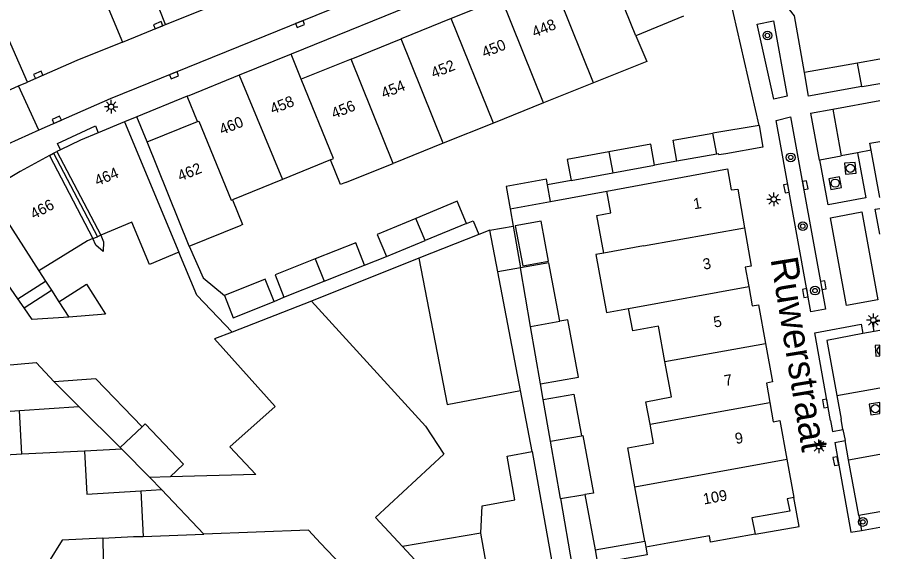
# Model space of a CAD drawing. Extents: x 132573 to 132944, y 398226 to 398676.
# Drawn here: x 132860.9 to 132940.1, y 398499.2 to 398548.2 of the extents above; entities that cross this region are included whole.
import ezdxf

# ---------------------------------------------------------------- set-up
doc = ezdxf.new("R2010")
doc.units = 0
for name, color, linetype in [('gg-afsc-erfafscheiding', 7, 'Continuous'), ('gg-afsc-muur', 7, 'Continuous'), ('gg-anno-huisnummerreeks BGT', 7, 'Continuous'), ('gg-anno-openbare ruimte label', 7, 'Continuous'), ('gg-bbg-bijgebouw', 7, 'Continuous'), ('gg-bbg-gedigitaliseerde bebouwing', 7, 'Continuous'), ('gg-bbg-gedigitaliseerde bebouwing onder overbouw', 7, 'Continuous'), ('gg-bbg-gedigitaliseerde bijgebouw', 7, 'Continuous'), ('gg-bbg-gedigitaliseerde overbouw', 7, 'Continuous'), ('gg-bbg-hoofdgebouw', 7, 'Continuous'), ('gg-bbg-luifel en loopbrug', 7, 'Continuous'), ('gg-bbg-onder overbouw', 7, 'Continuous'), ('gg-bbg-pand overbouw', 7, 'Continuous'), ('gg-bbg-tussenscheiding', 7, 'Continuous'), ('gg-bbg-tussenscheiding niveau 01', 7, 'Continuous'), ('gg-knt-verharding', 7, 'Continuous'), ('gg-knt-verharding nz', 7, 'Continuous'), ('gt-grn-groengrens', 7, 'Continuous'), ('gt-grn-vlakafsluiter', 7, 'Continuous'), ('gt-symb-boom', 7, 'Continuous'), ('gt-symb-kolk', 7, 'Continuous'), ('gt-symb-lichtmast', 7, 'Continuous'), ('gt-symb-rioolschacht', 7, 'Continuous')]:
    doc.layers.add(name, color=color, linetype=linetype)

msp = doc.modelspace()

# ---------------------------------------------------------------- linework, layer by layer
at = {"layer": 'gg-afsc-erfafscheiding'}
for p, q in [((132935.81, 398539.812), (132940.113, 398540.585)), ((132872.84, 398536.791), (132871.907, 398539.109)), ((132921.48, 398535.02), (132919.435, 398534.65)), ((132911.764, 398533.25), (132909.597, 398532.873)), ((132909.879, 398531.328), (132915.05, 398532.29)), ((132906.177, 398530.652), (132906.455, 398529.076)), ((132897.805, 398526.121), (132887.947, 398522.194)), ((132892.815, 398525.497), (132894.826, 398526.271)), ((132884.508, 398522.164), (132885.409, 398522.562)), ((132909.222, 398513.164), (132908.973, 398514.593)), ((132908.194, 398508.399), (132907.122, 398513.989))]:
    msp.add_line(p, q, dxfattribs=at)
for points in [[(132902.158, 398529.307), (132902.784, 398529.566), (132903.303, 398528.311)], [(132868.587, 398528.231), (132868.838, 398527.631), (132868.798, 398526.758), (132868.12, 398527.33), (132867.868, 398527.93)], [(132880.657, 398519.357), (132877.407, 398522.74), (132875.762, 398526.67)], [(132876.699, 398527.229), (132877.995, 398524.337), (132879.932, 398522.722)]]:
    msp.add_lwpolyline(points, dxfattribs=at)
at = {"layer": 'gg-afsc-muur'}
for p, q in [((132929.03, 398538.312), (132926.35, 398550.101)), ((132939.322, 398536.029), (132938.057, 398535.785)), ((132938.057, 398535.785), (132936.573, 398535.511)), ((132932.699, 398501.529), (132932.228, 398504.167)), ((132928.662, 398500.829), (132932.699, 398501.529))]:
    msp.add_line(p, q, dxfattribs=at)
msp.add_lwpolyline([(132933.193, 398543.17), (132932.27, 398548.361), (132931.02, 398549.991), (132930.646, 398551.538)], dxfattribs=at)
at = {"layer": 'gg-bbg-bijgebouw'}
for p, q in [((132938.075, 398544.033), (132933.193, 398543.17)), ((132940.113, 398544.393), (132938.075, 398544.033)), ((132933.58, 398540.991), (132933.193, 398543.17)), ((132938.47, 398541.864), (132933.58, 398540.991)), ((132938.47, 398541.864), (132938.491, 398541.868)), ((132938.491, 398541.868), (132940.113, 398542.157)), ((132933.759, 398539.438), (132935.81, 398539.812)), ((132935.81, 398539.812), (132936.573, 398535.511)), ((132929.03, 398538.312), (132924.8, 398537.585)), ((132929.03, 398538.312), (132929.383, 398536.329)), ((132929.383, 398536.329), (132925.981, 398535.715)), ((132925.142, 398535.679), (132921.48, 398535.02)), ((132934.605, 398535.141), (132936.573, 398535.511)), ((132902.158, 398529.307), (132898.375, 398527.741)), ((132894.826, 398526.271), (132898.375, 398527.741)), ((132889.109, 398524.028), (132892.815, 398525.497)), ((132885.409, 398522.562), (132889.109, 398524.028))]:
    msp.add_line(p, q, dxfattribs=at)
for points in [[(132933.759, 398539.438), (132934.554, 398535.131), (132934.605, 398535.141)], [(132921.48, 398535.02), (132921.143, 398536.956), (132924.8, 398537.585)], [(132925.981, 398535.715), (132925.337, 398535.599), (132925.317, 398535.71), (132925.142, 398535.679)], [(132902.158, 398529.307), (132901.317, 398531.35), (132897.53, 398529.782)], [(132897.53, 398529.782), (132893.98, 398528.311), (132894.826, 398526.271)], [(132892.815, 398525.497), (132892.002, 398527.551), (132888.274, 398526.074)], [(132888.274, 398526.074), (132884.595, 398524.616), (132885.409, 398522.562)], [(132884.508, 398522.164), (132883.693, 398524.215), (132879.932, 398522.722)], [(132879.932, 398522.722), (132880.749, 398520.67), (132884.508, 398522.164)]]:
    msp.add_lwpolyline(points, dxfattribs=at)
at = {"layer": 'gg-bbg-gedigitaliseerde bebouwing'}
for p, q in [((132870.75, 398538.641), (132875.762, 398526.67)), ((132862.911, 398524.963), (132863.512, 398524.031)), ((132860.969, 398522.391), (132863.512, 398524.031)), ((132887.947, 398522.194), (132880.657, 398519.357)), ((132874.958, 398506.073), (132873.101, 398506.023))]:
    msp.add_line(p, q, dxfattribs=at)
for points in [[(132914.764, 398526.589), (132914.132, 398530.046), (132915.422, 398530.283), (132915.05, 398532.29)], [(132875.762, 398526.67), (132873.068, 398525.542), (132871.441, 398529.427), (132868.587, 398528.231)], [(132867.868, 398527.93), (132867.363, 398527.718), (132862.911, 398524.963)], [(132914.764, 398526.589), (132914.046, 398526.457), (132915.032, 398521.152), (132917.051, 398521.52)], [(132860.969, 398522.391), (132858.839, 398525.456), (132855.502, 398523.243)], [(132880.657, 398519.357), (132879.037, 398518.727), (132884.59, 398512.541), (132880.441, 398508.817), (132882.835, 398506.285), (132874.958, 398506.073)]]:
    msp.add_lwpolyline(points, dxfattribs=at)
at = {"layer": 'gg-bbg-gedigitaliseerde bebouwing onder overbouw'}
for p, q in [((132863.872, 398535.546), (132867.868, 398527.93)), ((132864.562, 398535.903), (132868.587, 398528.231))]:
    msp.add_line(p, q, dxfattribs=at)
at = {"layer": 'gg-bbg-gedigitaliseerde bijgebouw'}
for p, q in [((132915.6, 398533.95), (132919.435, 398534.65)), ((132911.764, 398533.25), (132915.6, 398533.95)), ((132909.879, 398531.328), (132909.597, 398532.873)), ((132906.177, 398530.652), (132909.879, 398531.328)), ((132904.299, 398528.708), (132906.455, 398529.076)), ((132906.455, 398529.076), (132907.132, 398525.246)), ((132905.032, 398524.887), (132904.299, 398528.708)), ((132907.132, 398525.246), (132905.032, 398524.887)), ((132908.055, 398519.873), (132907.132, 398525.246)), ((132861.544, 398521.564), (132864.058, 398523.185)), ((132864.058, 398523.185), (132864.747, 398522.116)), ((132908.973, 398514.593), (132908.055, 398519.873)), ((132909.222, 398513.164), (132912.03, 398513.672)), ((132909.888, 398509.339), (132909.222, 398513.164)), ((132912.03, 398513.672), (132912.74, 398509.851)), ((132859.837, 398512.077), (132861.118, 398512.163)), ((132861.347, 398508.149), (132861.118, 398512.163)), ((132870.361, 398508.753), (132872.384, 398510.673)), ((132910.803, 398504.077), (132909.888, 398509.339)), ((132867.085, 398508.432), (132861.347, 398508.149)), ((132870.513, 398508.601), (132870.361, 398508.753)), ((132873.101, 398506.023), (132870.513, 398508.601)), ((132872.265, 398504.788), (132872.489, 398500.6)), ((132913.031, 398504.441), (132913.97, 398499.388)), ((132910.803, 398504.077), (132911.885, 398497.862)), ((132913.97, 398499.388), (132914.203, 398498.133))]:
    msp.add_line(p, q, dxfattribs=at)
for points in [[(132919.435, 398534.65), (132919.083, 398536.58), (132915.247, 398535.88)], [(132915.247, 398535.88), (132911.412, 398535.18), (132911.764, 398533.25)], [(132909.597, 398532.873), (132909.503, 398533.388), (132905.801, 398532.712), (132906.177, 398530.652)], [(132909.708, 398525.861), (132909.026, 398529.527), (132906.647, 398529.11), (132907.333, 398525.419), (132909.708, 398525.861)], [(132910.733, 398520.348), (132909.737, 398525.703), (132907.132, 398525.246)], [(132864.747, 398522.116), (132867.267, 398523.742), (132869.035, 398521.001), (132865.642, 398520.73)], [(132865.642, 398520.73), (132862.286, 398520.497), (132861.544, 398521.564)], [(132908.973, 398514.593), (132912.45, 398515.223), (132911.472, 398520.485), (132910.733, 398520.348)], [(132859.837, 398512.077), (132859.565, 398516.283), (132862.643, 398516.565), (132864.298, 398514.792)], [(132872.384, 398510.673), (132868.143, 398515.06), (132864.298, 398514.792)], [(132912.74, 398509.851), (132912.86, 398509.872), (132913.844, 398504.574), (132913.031, 398504.441)], [(132867.085, 398508.432), (132867.307, 398504.488), (132872.265, 398504.788)], [(132868.782, 398500.461), (132868.822, 398496.592), (132867.181, 398496.546), (132866.33, 398495.702)], [(132868.782, 398500.461), (132871.588, 398500.6), (132872.489, 398500.6)]]:
    msp.add_lwpolyline(points, dxfattribs=at)
at = {"layer": 'gg-bbg-gedigitaliseerde overbouw'}
for p in [(132867.868, 398527.93), (132868.587, 398528.231)]:
    msp.add_line(p, (132868.275, 398528.1), dxfattribs=at)
at = {"layer": 'gg-bbg-hoofdgebouw'}
for p, q in [((132905.367, 398549.981), (132900.775, 398548.121)), ((132900.775, 398548.121), (132896.183, 398546.261)), ((132922.085, 398548.337), (132917.731, 398546.536)), ((132891.592, 398544.401), (132896.183, 398546.261)), ((132886.06, 398544.851), (132881.304, 398542.92)), ((132887, 398542.541), (132886.06, 398544.851)), ((132891.592, 398544.401), (132887, 398542.541)), ((132881.304, 398542.92), (132876.66, 398541.034)), ((132913.827, 398542.218), (132909.23, 398540.371)), ((132876.66, 398541.034), (132876.53, 398540.981)), ((132877.47, 398538.661), (132876.53, 398540.981)), ((132909.23, 398540.371), (132904.633, 398538.523)), ((132870.75, 398538.641), (132868.354, 398537.642)), ((132872.84, 398536.791), (132877.47, 398538.661)), ((132904.633, 398538.523), (132900.037, 398536.676)), ((132876.699, 398527.229), (132872.84, 398536.791)), ((132939.205, 398536.674), (132940.113, 398536.837)), ((132864.884, 398536.061), (132864.562, 398535.903)), ((132900.037, 398536.676), (132895.44, 398534.827)), ((132939.322, 398536.029), (132939.205, 398536.674)), ((132940.113, 398531.685), (132939.322, 398536.029)), ((132889.682, 398535.15), (132885.261, 398533.355)), ((132891.059, 398533.067), (132895.44, 398534.827)), ((132915.05, 398532.29), (132926.12, 398534.333)), ((132885.261, 398533.355), (132880.678, 398531.494)), ((132876.699, 398527.229), (132881.468, 398529.17)), ((132908.194, 398508.399), (132909.704, 398500)), ((132931.59, 398507.692), (132932.228, 398504.167)), ((132918.532, 398500.182), (132917.627, 398505.17)), ((132909.704, 398500), (132910.135, 398497.605)), ((132918.532, 398500.182), (132918.63, 398499.639)), ((132920.664, 398500), (132918.63, 398499.639))]:
    msp.add_line(p, q, dxfattribs=at)
for points in [[(132917.731, 398546.536), (132918.719, 398544.185), (132913.827, 398542.218)], [(132868.354, 398537.642), (132866.72, 398536.961), (132864.884, 398536.061)], [(132863.872, 398535.546), (132861.179, 398534.096), (132858.174, 398532.307)], [(132891.059, 398533.067), (132890.602, 398532.883), (132889.682, 398535.15)], [(132926.12, 398534.333), (132926.469, 398532.387), (132927.069, 398532.476), (132927.696, 398528.93)], [(132880.678, 398531.494), (132881.598, 398529.223), (132881.468, 398529.17)], [(132940.113, 398528.329), (132939.697, 398530.623), (132940.113, 398530.698)], [(132927.696, 398528.93), (132928.318, 398525.414), (132927.758, 398525.301), (132928.082, 398523.529)], [(132928.082, 398523.529), (132928.403, 398521.77), (132928.993, 398521.847), (132929.637, 398518.305)], [(132887.947, 398522.194), (132898.401, 398510.734), (132900.085, 398508.167), (132893.819, 398502.346), (132896.299, 398499.682)], [(132920.39, 398516.661), (132919.788, 398519.903), (132917.433, 398519.465), (132917.051, 398521.52)], [(132929.637, 398518.305), (132930.278, 398514.784), (132929.699, 398514.66), (132930.021, 398512.888)], [(132919.021, 398510.922), (132918.64, 398512.969), (132920.995, 398513.407), (132920.39, 398516.661)], [(132930.021, 398512.888), (132930.341, 398511.125), (132930.948, 398511.234), (132931.59, 398507.692)], [(132917.627, 398505.17), (132916.983, 398508.722), (132919.348, 398509.162), (132919.021, 398510.922)], [(132903.474, 398500.903), (132903.601, 398503.404), (132906.602, 398503.958), (132905.893, 398507.977), (132908.194, 398508.399)], [(132932.228, 398504.167), (132931.627, 398504.061), (132931.842, 398502.937), (132928.382, 398502.323), (132928.662, 398500.829)], [(132928.662, 398500.829), (132924.579, 398500.086), (132924.472, 398500.676), (132920.664, 398500)]]:
    msp.add_lwpolyline(points, dxfattribs=at)
at = {"layer": 'gg-bbg-luifel en loopbrug'}
for p, q in [((132903.303, 398528.311), (132897.805, 398526.121)), ((132904.299, 398528.708), (132903.303, 398528.311)), ((132907.122, 398513.989), (132905.032, 398524.887)), ((132863.512, 398524.031), (132864.058, 398523.185)), ((132861.544, 398521.564), (132860.969, 398522.391)), ((132913.97, 398499.388), (132918.532, 398500.182))]:
    msp.add_line(p, q, dxfattribs=at)
for points in [[(132897.805, 398526.121), (132900.38, 398512.696), (132907.122, 398513.989)], [(132861.347, 398508.149), (132859.851, 398508.075), (132859.654, 398512.068), (132859.837, 398512.077)], [(132872.384, 398510.673), (132872.663, 398510.942), (132876.184, 398507.239), (132874.958, 398506.073)], [(132868.782, 398500.461), (132865.027, 398500.275), (132863.798, 398498.252)], [(132918.63, 398499.639), (132918.757, 398498.925), (132914.203, 398498.133)]]:
    msp.add_lwpolyline(points, dxfattribs=at)
at = {"layer": 'gg-bbg-onder overbouw'}
for points in [[(132904.422, 398493.346), (132904.388, 398493.537), (132904.506, 398493.558), (132904.463, 398493.843), (132904.75, 398493.886), (132903.474, 398500.903)], [(132901.235, 398492.774), (132901.192, 398492.963), (132901.075, 398492.936), (132900.469, 398495.203), (132896.299, 398499.682)]]:
    msp.add_lwpolyline(points, dxfattribs=at)
at = {"layer": 'gg-bbg-pand overbouw'}
for p, q in [((132863.872, 398535.546), (132864.259, 398535.754)), ((132864.259, 398535.754), (132864.562, 398535.903)), ((132903.474, 398500.903), (132896.299, 398499.682))]:
    msp.add_line(p, q, dxfattribs=at)
at = {"layer": 'gg-bbg-tussenscheiding'}
for p, q in [((132913.827, 398542.218), (132909.958, 398551.841)), ((132909.23, 398540.371), (132905.367, 398549.981)), ((132904.633, 398538.523), (132900.775, 398548.121)), ((132900.037, 398536.676), (132896.183, 398546.261)), ((132895.44, 398534.827), (132891.592, 398544.401)), ((132938.47, 398541.864), (132938.075, 398544.033)), ((132881.304, 398542.92), (132885.261, 398533.355)), ((132925.142, 398535.679), (132924.8, 398537.585)), ((132915.247, 398535.88), (132915.6, 398533.95)), ((132858.174, 398532.307), (132862.911, 398524.963)), ((132898.375, 398527.741), (132897.53, 398529.782)), ((132918.421, 398527.258), (132927.696, 398528.93)), ((132918.421, 398527.258), (132914.764, 398526.589)), ((132888.274, 398526.074), (132889.109, 398524.028)), ((132917.051, 398521.52), (132928.082, 398523.529)), ((132864.747, 398522.116), (132865.642, 398520.73)), ((132908.055, 398519.873), (132910.733, 398520.348)), ((132920.39, 398516.661), (132929.637, 398518.305)), ((132866.57, 398512.529), (132864.298, 398514.792)), ((132861.118, 398512.163), (132866.57, 398512.529)), ((132870.361, 398508.753), (132866.57, 398512.529)), ((132919.021, 398510.922), (132930.021, 398512.888)), ((132909.888, 398509.339), (132912.74, 398509.851)), ((132870.513, 398508.601), (132867.085, 398508.432)), ((132917.627, 398505.17), (132931.59, 398507.692)), ((132874.166, 398504.903), (132873.101, 398506.023)), ((132872.265, 398504.788), (132874.166, 398504.903)), ((132874.166, 398504.903), (132878.06, 398500.809)), ((132910.803, 398504.077), (132913.031, 398504.441)), ((132872.489, 398500.6), (132878.06, 398500.809)), ((132891.398, 398497.229), (132888.777, 398500))]:
    msp.add_line(p, q, dxfattribs=at)
for points in [[(132917.731, 398546.536), (132914.793, 398553.799), (132914.55, 398553.701)], [(132889.682, 398535.15), (132889.961, 398535.263), (132887, 398542.541)], [(132877.47, 398538.661), (132877.6, 398538.714), (132880.547, 398531.441), (132880.678, 398531.494)], [(132888.777, 398500), (132887.671, 398501.17), (132878.06, 398500.809)]]:
    msp.add_lwpolyline(points, dxfattribs=at)
at = {"layer": 'gg-bbg-tussenscheiding niveau 01'}
msp.add_line((132864.259, 398535.754), (132868.275, 398528.1), dxfattribs=at)
at = {"layer": 'gg-knt-verharding'}
for p, q in [((132913.61, 398556.031), (132886.06, 398544.851)), ((132874.532, 398547.556), (132872.221, 398553.404)), ((132868.18, 398551.756), (132870.582, 398545.942)), ((132861.856, 398542.29), (132859.304, 398548)), ((132870.582, 398545.942), (132874.532, 398547.556)), ((132861.045, 398541.93), (132861.856, 398542.29)), ((132862.897, 398537.875), (132861.045, 398541.93)), ((132876.53, 398540.981), (132871.907, 398539.109)), ((132871.907, 398539.109), (132870.75, 398538.641)), ((132862.897, 398537.875), (132858.535, 398535.906)), ((132933.796, 398521.196), (132931.013, 398536.586)), ((132940.113, 398519.496), (132939.591, 398519.403)), ((132935.602, 398511.242), (132934.14, 398519.294)), ((132936.172, 398513.526), (132936.568, 398511.374)), ((132935.602, 398511.242), (132935.788, 398510.241)), ((132936.727, 398510.433), (132936.568, 398511.374)), ((132935.788, 398510.241), (132936.727, 398510.433)), ((132935.976, 398509.228), (132936.933, 398509.398)), ((132935.976, 398509.228), (132937.46, 398500.988)), ((132937.251, 398507.648), (132936.933, 398509.398)), ((132938.19, 398502.527), (132937.251, 398507.648)), ((132940.113, 398502.879), (132938.19, 398502.527)), ((132937.46, 398500.988), (132938.44, 398501.165)), ((132938.44, 398501.165), (132940.113, 398501.468))]:
    msp.add_line(p, q, dxfattribs=at)
for points in [[(132922.48, 398562.197), (132915.452, 398559.401), (132869.443, 398540.745), (132862.897, 398537.875)], [(132928.866, 398547.6), (132930.357, 398547.898), (132931.602, 398540.994), (132930.399, 398540.729), (132928.866, 398547.6)], [(132856.665, 398539.883), (132858.71, 398540.892), (132861.045, 398541.93)], [(132931.013, 398536.586), (132930.616, 398538.77), (132931.932, 398539.091)], [(132931.932, 398539.091), (132935.129, 398521.454), (132933.796, 398521.196)], [(132864.884, 398536.061), (132864.602, 398536.636), (132868.096, 398538.26), (132868.354, 398537.642)], [(132938.057, 398535.785), (132938.833, 398531.668), (132935.367, 398531.015), (132934.605, 398535.141)], [(132935.593, 398529.84), (132938.46, 398530.369), (132939.93, 398522.32), (132937.055, 398521.793), (132935.593, 398529.84)], [(132939.591, 398519.403), (132939.443, 398520.26), (132940.113, 398520.384)], [(132934.14, 398519.294), (132938.417, 398520.077), (132938.571, 398519.222)], [(132938.571, 398519.222), (132935.26, 398518.593), (132936.172, 398513.526)]]:
    msp.add_lwpolyline(points, dxfattribs=at)
at = {"layer": 'gg-knt-verharding nz'}
for p, q in [((132874.532, 398547.556), (132883.53, 398551.178)), ((132936.172, 398513.526), (132940.113, 398514.241)), ((132937.251, 398507.648), (132940.113, 398508.168))]:
    msp.add_line(p, q, dxfattribs=at)
msp.add_lwpolyline([(132870.582, 398545.942), (132866.381, 398544.249), (132861.856, 398542.29)], dxfattribs=at)
at = {"layer": 'gt-grn-groengrens'}
msp.add_line((132938.19, 398502.527), (132938.44, 398501.165), dxfattribs=at)
at = {"layer": 'gt-grn-vlakafsluiter'}
for p, q in [((132939.591, 398519.403), (132938.571, 398519.222)), ((132936.727, 398510.433), (132936.933, 398509.398))]:
    msp.add_line(p, q, dxfattribs=at)
at = {"layer": 'gt-symb-boom'}
for centre, radius in [((132929.798, 398546.558), 0.4), ((132929.798, 398546.558), 0.2), ((132931.934, 398535.378), 0.4), ((132931.934, 398535.378), 0.2), ((132933.048, 398529.069), 0.4), ((132933.048, 398529.069), 0.2), ((132934.168, 398523.158), 0.4), ((132934.168, 398523.158), 0.2), ((132938.562, 398501.936), 0.4), ((132938.562, 398501.936), 0.2)]:
    msp.add_circle(centre, radius, dxfattribs=at)
at = {"layer": 'gt-symb-kolk'}
for points in [[(132886.809, 398547.787), (132886.461, 398547.646), (132886.611, 398547.276), (132887.307, 398547.557), (132887.157, 398547.928), (132886.809, 398547.787)], [(132873.939, 398547.316), (132874.286, 398547.458), (132874.134, 398547.828), (132873.44, 398547.544), (132873.592, 398547.174), (132873.939, 398547.316)], [(132862.924, 398542.77), (132863.267, 398542.922), (132863.104, 398543.288), (132862.419, 398542.983), (132862.581, 398542.618), (132862.924, 398542.77)], [(132875.238, 398543.095), (132874.89, 398542.955), (132875.04, 398542.584), (132875.735, 398542.864), (132875.586, 398543.235), (132875.238, 398543.095)], [(132864.626, 398538.65), (132864.969, 398538.801), (132864.807, 398539.167), (132864.121, 398538.864), (132864.283, 398538.499), (132864.626, 398538.65)], [(132931.744, 398532.558), (132931.678, 398532.927), (132931.284, 398532.856), (132931.417, 398532.118), (132931.81, 398532.189), (132931.744, 398532.558)], [(132933.074, 398532.79), (132933.141, 398532.421), (132933.535, 398532.493), (132933.4, 398533.231), (132933.007, 398533.159), (132933.074, 398532.79)], [(132933.476, 398522.967), (132933.41, 398523.336), (132933.016, 398523.265), (132933.149, 398522.527), (132933.542, 398522.598), (132933.476, 398522.967)], [(132934.735, 398523.626), (132934.802, 398523.257), (132935.196, 398523.329), (132935.061, 398524.067), (132934.668, 398523.995), (132934.735, 398523.626)], [(132935.312, 398512.84), (132935.245, 398513.209), (132934.851, 398513.137), (132934.986, 398512.399), (132935.379, 398512.471), (132935.312, 398512.84)], [(132936.279, 398507.545), (132936.212, 398507.914), (132935.818, 398507.842), (132935.953, 398507.104), (132936.346, 398507.176), (132936.279, 398507.545)]]:
    msp.add_lwpolyline(points, dxfattribs=at)
at = {"layer": 'gt-symb-lichtmast'}
for p, q in [((132869.289, 398540.022), (132868.914, 398540.022)), ((132869.362, 398540.199), (132869.097, 398540.464)), ((132869.539, 398540.272), (132869.539, 398540.647)), ((132869.716, 398540.199), (132869.981, 398540.464)), ((132869.789, 398540.022), (132870.164, 398540.022)), ((132869.362, 398539.845), (132869.097, 398539.58)), ((132869.539, 398539.772), (132869.539, 398539.397)), ((132869.981, 398539.58), (132869.716, 398539.845)), ((132930.381, 398531.775), (132930.381, 398532.15)), ((132930.131, 398531.525), (132929.756, 398531.525)), ((132930.204, 398531.702), (132929.939, 398531.967)), ((132930.204, 398531.348), (132929.939, 398531.083)), ((132930.381, 398531.275), (132930.381, 398530.9)), ((132930.558, 398531.702), (132930.823, 398531.967)), ((132930.823, 398531.083), (132930.558, 398531.348)), ((132930.631, 398531.525), (132931.006, 398531.525)), ((132939.525, 398520.692), (132939.525, 398521.067)), ((132939.275, 398520.442), (132938.9, 398520.442)), ((132939.348, 398520.619), (132939.083, 398520.884)), ((132939.348, 398520.265), (132939.083, 398520)), ((132939.525, 398520.192), (132939.525, 398519.817)), ((132939.702, 398520.619), (132939.967, 398520.884)), ((132939.967, 398520), (132939.702, 398520.265)), ((132939.775, 398520.442), (132940.113, 398520.442)), ((132934.354, 398509.059), (132934.089, 398509.324)), ((132934.531, 398509.132), (132934.531, 398509.507)), ((132934.708, 398509.059), (132934.973, 398509.324)), ((132934.281, 398508.882), (132933.906, 398508.882)), ((132934.354, 398508.705), (132934.089, 398508.44)), ((132934.531, 398508.632), (132934.531, 398508.257)), ((132934.973, 398508.44), (132934.708, 398508.705)), ((132934.781, 398508.882), (132935.156, 398508.882))]:
    msp.add_line(p, q, dxfattribs=at)
for centre in [(132869.539, 398540.022), (132930.381, 398531.525), (132939.525, 398520.442), (132934.531, 398508.882)]:
    msp.add_circle(centre, 0.25, dxfattribs=at)
at = {"layer": 'gt-symb-rioolschacht'}
msp.add_line((132940.113, 398517.313), (132940.113, 398518.029), dxfattribs=at)
for points in [[(132937.871, 398534.921), (132936.875, 398534.837), (132936.959, 398533.841), (132937.955, 398533.925)], [(132935.623, 398532.426), (132936.607, 398532.608), (132936.425, 398533.592), (132935.441, 398533.41)], [(132940.113, 398517.16), (132940.113, 398518.164), (132939.686, 398518.129), (132939.767, 398517.132)], [(132940.113, 398511.89), (132940.113, 398512.904), (132939.136, 398512.738), (132939.303, 398511.753)]]:
    msp.add_lwpolyline(points, close=True, dxfattribs=at)
for centre in [(132937.415, 398534.381), (132936.024, 398533.009), (132939.712, 398512.329)]:
    msp.add_circle(centre, 0.375, dxfattribs=at)
msp.add_arc((132940.225, 398517.671), 0.375, 107.38401, 252.61599, dxfattribs=at)

# ---------------------------------------------------------------- texts
at = {"layer": 'gg-anno-huisnummerreeks BGT'}
for s, rotation, p in [('448', 22, (132908.417, 398546.362)), ('450', 22, (132903.815, 398544.497)), ('452', 22, (132899.15, 398542.608)), ('454', 22, (132894.571, 398540.753)), ('458', 22.1, (132884.377, 398539.311)), ('456', 22, (132889.997, 398538.9)), ('460', 22.1, (132879.715, 398537.418)), ('464', 22.6, (132868.267, 398532.732)), ('462', 22, (132875.882, 398533.166)), ('466', 28.3, (132862.446, 398529.668)), ('1', 9.9, (132923.073, 398530.607)), ('3', 9.9, (132923.955, 398525.07)), ('5', 10.3, (132924.94, 398519.757)), ('7', 10.3, (132925.92, 398514.396)), ('9', 10.3, (132926.91, 398509.076)), ('109', 10.3, (132923.976, 398503.534))]:
    msp.add_text(s, height=1, rotation=rotation, dxfattribs=at).set_placement(p)
at = {"layer": 'gg-anno-openbare ruimte label'}
msp.add_text('Ruwerstraat', height=2.5, rotation=279.3, dxfattribs=at).set_placement((132930.077, 398526.052))

doc.saveas('drawing.dxf')
